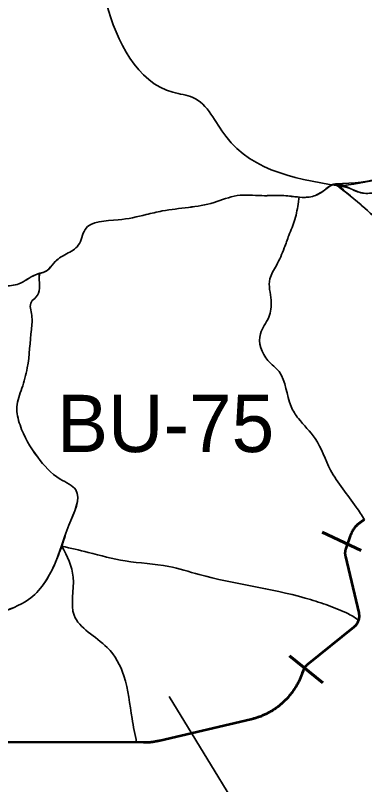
# Model space of a CAD drawing. Extents: x 553962 to 842807, y 8883888 to 9032388.
# Drawn here: x 661743 to 664180, y 8952165 to 8957536 of the extents above; entities that cross this region are included whole.
import ezdxf

# ---------------------------------------------------------------- set-up
doc = ezdxf.new("R2010")
doc.units = 0
doc.header["$LTSCALE"] = 150
for name, color, linetype, lineweight in [('20', 7, 'Continuous', 35), ('40', 7, 'Continuous', 60), ('60', 7, 'Continuous', 53), ('9', 7, 'Continuous', 90)]:
    doc.layers.add(name, color=color, linetype=linetype, lineweight=lineweight)

msp = doc.modelspace()

# ---------------------------------------------------------------- linework, layer by layer
at = {"layer": '20'}
for p, q in [((663983.2, 8956359), (663981.1, 8956359)), ((663983, 8956359.5), (663983.2, 8956359)), ((663725.2, 8956265.6), (663722.5, 8956265.9)), ((661914.8, 8955735.4), (661908.2, 8955709)), ((662067.8, 8953829.4), (662068, 8953829.2)), ((662068, 8953829.2), (662068.4, 8953831.3))]:
    msp.add_line(p, q, dxfattribs=at)
for points in [[(664136.3, 8953310.4), (664136.4, 8953310.8), (664137.2, 8953313.5), (664138, 8953316.2), (664138.6, 8953319), (664139.2, 8953321.8), (664139.7, 8953324.5), (664140.1, 8953327.3), (664140.5, 8953330.1), (664140.7, 8953333), (664140.9, 8953335.8), (664141, 8953338.6), (664141, 8953341.4), (664141, 8953344.3), (664140.8, 8953347.1), (664140.6, 8953349.9), (664140.3, 8953352.7), (664139.9, 8953355.5), (664139.5, 8953358.3), (664139, 8953361.1), (664138.3, 8953363.8), (664045.4, 8953756.9), (664045.3, 8953757.1), (664044.7, 8953759.9), (664044.2, 8953762.7), (664043.7, 8953765.5), (664043.4, 8953768.3), (664043.1, 8953771.1), (664042.9, 8953773.9), (664042.7, 8953776.7), (664042.7, 8953779.6), (664042.7, 8953782.4), (664042.8, 8953785.2), (664043, 8953788), (664043.3, 8953790.9), (664043.6, 8953793.7), (664044.1, 8953796.5), (664044.6, 8953799.2), (664045.2, 8953802), (664045.8, 8953804.8), (664046.6, 8953807.5), (664047.4, 8953810.2), (664048.3, 8953812.9), (664078.8, 8953900.5), (664078.9, 8953900.7), (664080.3, 8953904.5), (664081.7, 8953908.2), (664083.2, 8953911.9), (664084.8, 8953915.6), (664086.5, 8953919.2), (664088.2, 8953922.8), (664090, 8953926.4), (664091.9, 8953930), (664093.8, 8953933.5), (664095.8, 8953936.9), (664097.9, 8953940.3), (664100, 8953943.7), (664102.3, 8953947), (664104.5, 8953950.3), (664106.9, 8953953.6), (664109.3, 8953956.8), (664111.8, 8953959.9), (664114.3, 8953963), (664116.9, 8953966), (664119.6, 8953969), (664122.3, 8953972), (664125.1, 8953974.8), (664127.9, 8953977.7), (664130.8, 8953980.4), (664133.7, 8953983.1), (664136.7, 8953985.8), (664139.8, 8953988.4), (664142.9, 8953990.9), (664146, 8953993.4), (664149.2, 8953995.8), (664152.5, 8953998.1), (664155.8, 8954000.4), (664159.1, 8954002.6), (664162.5, 8954004.7), (664165.9, 8954006.8), (664169.4, 8954008.8), (664172.9, 8954010.7), (664176.4, 8954012.6), (664178.1, 8954013.4)], [(664109.7, 8953268.1), (664111.7, 8953270.1), (664113.7, 8953272.1), (664115.6, 8953274.2), (664117.4, 8953276.3), (664119.2, 8953278.5), (664121, 8953280.8), (664122.6, 8953283), (664124.2, 8953285.4), (664125.8, 8953287.7), (664127.2, 8953290.2), (664128.6, 8953292.6), (664130, 8953295.1), (664131.2, 8953297.6), (664132.4, 8953300.2), (664133.5, 8953302.8), (664134.6, 8953305.4), (664135.5, 8953308.1), (664135.7, 8953308.5)], [(663413.5, 8952626.8), (663419.5, 8952628.7), (663425.6, 8952630.6), (663431.6, 8952632.6), (663437.5, 8952634.6), (663443.5, 8952636.7), (663449.4, 8952638.9), (663455.3, 8952641.2), (663461.2, 8952643.6), (663467, 8952646), (663472.8, 8952648.5), (663478.6, 8952651.1), (663484.4, 8952653.7), (663490.1, 8952656.4), (663495.8, 8952659.2), (663501.4, 8952662.1), (663507, 8952665), (663512.6, 8952668), (663518.1, 8952671.1), (663523.6, 8952674.2), (663529, 8952677.5), (663534.4, 8952680.7), (663539.8, 8952684.1), (663545.1, 8952687.5), (663550.4, 8952691), (663555.6, 8952694.6), (663560.8, 8952698.2), (663566, 8952701.8), (663571.1, 8952705.6), (663576.1, 8952709.4), (663581.1, 8952713.3), (663586, 8952717.2), (663590.9, 8952721.2), (663595.8, 8952725.3), (663600.6, 8952729.4), (663605.3, 8952733.6), (663610, 8952737.8), (663614.7, 8952742.1), (663619.2, 8952746.5), (663623.8, 8952750.9), (663628.2, 8952755.4), (663632.6, 8952759.9), (663637, 8952764.5), (663641.3, 8952769.2), (663645.5, 8952773.8), (663649.7, 8952778.6), (663653.8, 8952783.4), (663657.9, 8952788.2), (663661.9, 8952793.2), (663665.8, 8952798.1), (663669.7, 8952803.1), (663673.5, 8952808.2), (663677.2, 8952813.3), (663680.9, 8952818.4), (663684.5, 8952823.6), (663688.1, 8952828.8), (663691.5, 8952834.1), (663694.9, 8952839.4), (663698.3, 8952844.8), (663701.6, 8952850.2), (663704.8, 8952855.7), (663707.9, 8952861.2), (663711, 8952866.7), (663714, 8952872.3), (663716.9, 8952877.9), (663719.8, 8952883.5), (663722.5, 8952889.2), (663725.2, 8952894.9), (663727.9, 8952900.7), (663730.5, 8952906.4), (663733, 8952912.2), (663735.4, 8952918.1), (663737.7, 8952924), (663740, 8952929.9), (663742.2, 8952935.8), (663744.3, 8952941.8), (663750.3, 8952958.8), (663750.9, 8952960.7), (663752, 8952963.3), (663753.1, 8952965.9), (663754.2, 8952968.5), (663755.5, 8952971.1), (663756.8, 8952973.6), (663758.2, 8952976), (663759.6, 8952978.5), (663761.1, 8952980.8), (663762.7, 8952983.2), (663764.4, 8952985.5), (663766.1, 8952987.7), (663767.9, 8952989.9), (663769.7, 8952992.1), (663771.6, 8952994.2), (663773.6, 8952996.2), (663775.6, 8952998.2), (663777.7, 8953000.1), (663779.8, 8953002), (663782, 8953003.8), (664103.8, 8953263), (664105.4, 8953264.3), (664107.6, 8953266.2), (664109.7, 8953268.1)], [(662589.5, 8952457.7), (662636.4, 8952457.6), (662639.1, 8952457.6), (662645.4, 8952457.6), (662651.7, 8952457.8), (662658, 8952458), (662664.3, 8952458.3), (662670.7, 8952458.7), (662677, 8952459.1), (662683.3, 8952459.7), (662689.6, 8952460.3), (662695.8, 8952461), (662702.1, 8952461.8), (662708.4, 8952462.6), (662714.7, 8952463.5), (662720.9, 8952464.6), (662727.1, 8952465.7), (662733.3, 8952466.8), (662739.5, 8952468.1), (662745.7, 8952469.4), (662751.9, 8952470.8), (663386.4, 8952619.7), (663389, 8952620.3), (663395.2, 8952621.8), (663401.3, 8952623.4), (663407.4, 8952625.1), (663413.5, 8952626.8)], [(661588, 8952460.2), (662586.9, 8952457.7)]]:
    msp.add_lwpolyline(points, dxfattribs=at)
for points in [[(658364.9, 8962599.6), (658556.5, 8962502.9), (659045.7, 8962575.2), (659677.7, 8962855.9), (660030.7, 8963073.8), (660994.7, 8963383.9), (661225.1, 8963375.6), (661485.9, 8963334), (661784, 8963142), (662145.1, 8962868.4), (662304.1, 8962730.4), (662407.6, 8962635.8), (662485.7, 8962526), (662573.8, 8962395.9), (662618.6, 8962222.6), (662640.7, 8962049.3), (662647.4, 8961832.8), (662600.5, 8961517.2), (662472.3, 8961166.2), (662328.2, 8960647.1), (662136.1, 8960143.5), (662172.6, 8959188.3), (662226.8, 8958808.7), (662270.5, 8958368), (662304.7, 8958064.8), (662378.8, 8957618.9), (662842.3, 8956998.6), (662981.5, 8956962.5), (663210.9, 8956691.8), (664058.5, 8956334.7)], [(663981.1, 8956359), (664321.5, 8956411.5), (664614.4, 8956608.1), (664864.3, 8956815.9), (665021.3, 8956998.4), (665311.2, 8957255.6), (665395.6, 8957334.1), (665677.4, 8957354.5), (665753.9, 8957347.5), (666009.5, 8957272.9), (666473.5, 8957092.1), (666601, 8956857), (666580.9, 8956718.8), (666458.2, 8956568.3), (666403.9, 8956491.1)], [(664028.5, 8956347.9), (664321.5, 8956411.5), (664614.4, 8956608.1), (664864.3, 8956815.9), (665021.3, 8956998.4), (665311.2, 8957255.6), (665395.6, 8957334.1), (665677.4, 8957354.5), (665753.9, 8957347.5), (666009.5, 8957272.9), (666473.5, 8957092.1), (666601, 8956857), (666580.9, 8956718.8), (666458.2, 8956568.3), (666395.8, 8956461.5), (666396.3, 8956401), (666405.5, 8956143.7), (666460.3, 8955877.6), (666486.7, 8955602.2), (666567.1, 8955262.4)], [(658265.6, 8954703.8), (658307.9, 8954697.9), (658477.4, 8954686), (658784.8, 8954711.4), (658906.1, 8954671.9), (659120.4, 8954604.2), (659357.3, 8954511.1), (659671.5, 8954424.1), (659815.3, 8954446.7), (659930.9, 8954686.6), (660012.7, 8954833.3), (660207.3, 8954937.7), (660675.5, 8955107.1), (660909.5, 8955188.9), (660962, 8955262.3), (660987.4, 8955304.6), (661066.3, 8955341.3), (661139.7, 8955386.4), (661204.5, 8955507.8), (661229.9, 8955575.5), (661294.8, 8955586.8), (661382.2, 8955586.8), (661505.5, 8955628), (661660.6, 8955644.9), (661767.7, 8955661.9), (661883.4, 8955724), (661965.2, 8955755), (662010.3, 8955805.8), (662100.5, 8955870.7), (662182.3, 8955930), (662229.4, 8956040), (662460.7, 8956107.8), (662655.3, 8956144.4), (662768.1, 8956169.8), (663129.1, 8956229.1), (663289.8, 8956276.8), (663461.8, 8956276.8), (663617, 8956276.8), (663815.8, 8956271.2), (663900.4, 8956316.3), (663976.5, 8956358.6), (664083.7, 8956324.8), (664176.8, 8956293.7), (664227.5, 8956293.7), (664439.1, 8956265.5), (664543.4, 8956211.9), (664670.3, 8956189.3)], [(664014.5, 8956353.1), (663976.5, 8956358.6), (663900.4, 8956316.3), (663815.8, 8956271.2), (663617, 8956276.8), (663461.8, 8956276.8), (663289.8, 8956276.8), (663129.1, 8956229.1), (662768.1, 8956169.8), (662655.3, 8956144.4), (662460.7, 8956107.8), (662229.4, 8956040), (662182.3, 8955930), (662100.5, 8955870.7), (662010.3, 8955805.8), (661965.2, 8955755), (661883.4, 8955724), (661767.7, 8955661.9), (661660.6, 8955644.9), (661505.5, 8955628), (661382.2, 8955586.8), (661294.8, 8955586.8), (661229.9, 8955575.5), (661204.5, 8955507.8), (661139.7, 8955386.4), (661066.3, 8955341.3), (660987.4, 8955304.6), (660962, 8955262.3), (660909.5, 8955188.9), (660675.5, 8955107.1), (660207.3, 8954937.7), (660012.7, 8954833.3), (659930.9, 8954686.6), (659815.3, 8954446.7), (659671.5, 8954424.1), (659357.3, 8954511.1), (659120.4, 8954604.2), (658906.1, 8954671.9), (658784.8, 8954711.4), (658477.4, 8954686), (658307.9, 8954697.9), (658265.6, 8954703.8)], [(663980.8, 8956358.9), (663976.5, 8956358.6), (663900.4, 8956316.3), (663815.8, 8956271.2), (663725.2, 8956265.6)], [(664755.7, 8954053.1), (664609.6, 8954383.1), (664511, 8954645), (664477, 8954750.4), (664388.6, 8954978.3), (664378.4, 8955318.5), (664378.4, 8955556.6), (664412.4, 8955879.7), (664181.2, 8956189.3), (663977.3, 8956356)], [(664755.7, 8954053.1), (664609.6, 8954383.1), (664511, 8954645), (664477, 8954750.4), (664388.6, 8954978.3), (664378.4, 8955318.5), (664378.4, 8955556.6), (664412.4, 8955879.7), (664181.2, 8956189.3), (663983, 8956359.5)], [(664755.7, 8954053.1), (664609.6, 8954383.1), (664511, 8954645), (664477, 8954750.4), (664388.6, 8954978.3), (664378.4, 8955318.5), (664378.4, 8955556.6), (664412.4, 8955879.7), (664181.2, 8956189.3), (663983, 8956359.5)], [(663983.2, 8956359), (664083.7, 8956324.8), (664176.8, 8956293.7), (664227.5, 8956293.7), (664439.1, 8956265.5), (664543.4, 8956211.9), (664670.3, 8956189.3)], [(664670.3, 8956189.3), (664543.4, 8956211.9), (664439.1, 8956265.5), (664227.5, 8956293.7), (664176.8, 8956293.7), (664083.7, 8956324.8), (663983.2, 8956359)], [(663723.7, 8956265.8), (663617, 8956276.8), (663461.8, 8956276.8), (663289.8, 8956276.8), (663129.1, 8956229.1), (662768.1, 8956169.8), (662655.3, 8956144.4), (662460.7, 8956107.8), (662229.4, 8956040), (662182.3, 8955930), (662100.5, 8955870.7), (662010.3, 8955805.8), (661965.2, 8955755), (661914.8, 8955735.4)], [(664179.3, 8954014.1), (664121.2, 8954102.5), (664027.1, 8954229.8), (663942.3, 8954361.1), (663834.3, 8954581.1), (663717.6, 8954721.7), (663667.2, 8954803.9), (663582.4, 8955047.9), (663505.5, 8955124.9), (663452.5, 8955313.2), (663510.8, 8955427.3), (663526.8, 8955546.6), (663518.8, 8955695.2), (663563.9, 8955789.6), (663619.5, 8955911.7), (663651.3, 8955999.2), (663693.8, 8956110.6), (663717.6, 8956232.6), (663722.5, 8956265.9)], [(663722.5, 8956265.9), (663717.6, 8956232.6), (663693.8, 8956110.6), (663651.3, 8955999.2), (663619.5, 8955911.7), (663563.9, 8955789.6), (663518.8, 8955695.2), (663526.8, 8955546.6), (663510.8, 8955427.3), (663452.5, 8955313.2), (663505.5, 8955124.9), (663582.4, 8955047.9), (663667.2, 8954803.9), (663717.6, 8954721.7), (663834.3, 8954581.1), (663942.3, 8954361.1), (664027.1, 8954229.8), (664121.2, 8954102.5), (664179.3, 8954014.1)], [(664179.3, 8954014.1), (664121.2, 8954102.5), (664027.1, 8954229.8), (663942.3, 8954361.1), (663834.3, 8954581.1), (663717.6, 8954721.7), (663667.2, 8954803.9), (663582.4, 8955047.9), (663505.5, 8955124.9), (663452.5, 8955313.2), (663510.8, 8955427.3), (663526.8, 8955546.6), (663518.8, 8955695.2), (663563.9, 8955789.6), (663619.5, 8955911.7), (663651.3, 8955999.2), (663693.8, 8956110.6), (663717.6, 8956232.6), (663722.5, 8956265.9)], [(659729.1, 8954415.6), (659815.3, 8954446.7), (659930.9, 8954686.6), (660012.7, 8954833.3), (660207.3, 8954937.7), (660675.5, 8955107.1), (660909.5, 8955188.9), (660962, 8955262.3), (660987.4, 8955304.6), (661066.3, 8955341.3), (661139.7, 8955386.4), (661204.5, 8955507.8), (661229.9, 8955575.5), (661294.8, 8955586.8), (661382.2, 8955586.8), (661505.5, 8955628), (661660.6, 8955644.9), (661767.7, 8955661.9), (661883.4, 8955724), (661914.3, 8955735.2)], [(661908.2, 8955709), (661910.2, 8955723.1), (661914.1, 8955735.2)], [(660977.5, 8952920.6), (661096, 8952973), (661231.9, 8952979.3), (661427.8, 8953197.5), (661626.9, 8953355.6), (661835.5, 8953456.8), (662015.6, 8953700.3), (662116.8, 8953975.5), (662164.2, 8954222.1), (662056.7, 8954298), (661898.7, 8954449.8), (661775.5, 8954675.6), (661753.3, 8954802.1), (661788.1, 8954931.7), (661826, 8955074), (661854.5, 8955342.8), (661857.6, 8955440.8), (661854.5, 8955535.7), (661886.1, 8955567.3), (661908.2, 8955709)], [(661908.2, 8955709), (661886.1, 8955567.3), (661854.5, 8955535.7), (661857.6, 8955440.8), (661854.5, 8955342.8), (661826, 8955074), (661788.1, 8954931.7), (661753.3, 8954802.1), (661775.5, 8954675.6), (661898.7, 8954449.8), (662056.7, 8954298), (662164.2, 8954222.1), (662116.8, 8953975.5), (662069, 8953832.8)], [(661908.2, 8955709), (661886.1, 8955567.3), (661854.5, 8955535.7), (661857.6, 8955440.8), (661854.5, 8955342.8), (661826, 8955074), (661788.1, 8954931.7), (661753.3, 8954802.1), (661775.5, 8954675.6), (661898.7, 8954449.8), (662056.7, 8954298), (662164.2, 8954222.1), (662116.8, 8953975.5), (662069, 8953832.8)], [(662068.4, 8953831.3), (662015.6, 8953700.3), (661835.5, 8953456.8), (661626.9, 8953355.6), (661427.8, 8953197.5), (661231.9, 8952979.3), (661096, 8952973), (660977.5, 8952920.6)], [(662068.4, 8953831.3), (662015.6, 8953700.3), (661835.5, 8953456.8), (661626.9, 8953355.6), (661427.8, 8953197.5), (661231.9, 8952979.3), (661096, 8952973), (660977.5, 8952920.6)], [(663911.6, 8953421.1), (663764.6, 8953467), (663025.1, 8953631.4), (662813.3, 8953688.3), (662509.9, 8953726.3), (662250.8, 8953786.3), (662067.8, 8953829.4)], [(662067.8, 8953829.4), (662250.8, 8953786.3), (662509.9, 8953726.3), (662813.3, 8953688.3), (663025.1, 8953631.4), (663764.6, 8953467), (663911.6, 8953421.1)], [(663911.6, 8953421.1), (663764.6, 8953467), (663025.1, 8953631.4), (662813.3, 8953688.3), (662509.9, 8953726.3), (662250.8, 8953786.3), (662067.8, 8953829.4)], [(662589, 8952457.7), (662557.3, 8952625.8), (662500.5, 8952923), (662383.5, 8953122.2), (662152.8, 8953346.8), (662146.5, 8953612.4), (662068, 8953829.3)], [(662589, 8952457.7), (662557.3, 8952625.8), (662500.5, 8952923), (662383.5, 8953122.2), (662152.8, 8953346.8), (662146.5, 8953612.4), (662068, 8953829.2)], [(662068, 8953829.2), (662146.5, 8953612.4), (662152.8, 8953346.8), (662383.5, 8953122.2), (662500.5, 8952923), (662557.3, 8952625.8), (662589, 8952457.7)], [(664136.7, 8953311.8), (664123.6, 8953322.2), (664048.3, 8953365.5), (663909.6, 8953421.4)], [(663909.6, 8953421.4), (664048.3, 8953365.5), (664123.6, 8953322.2), (664136.7, 8953311.8)]]:
    msp.add_spline(points, degree=3, dxfattribs=at)
at = {"layer": '40'}
for p, q in [((664155.7, 8953799.8), (663883.7, 8953926.3)), ((663655.3, 8953063), (663889, 8952874.9))]:
    msp.add_line(p, q, dxfattribs=at)
at = {"layer": '40', "lineweight": 35}
msp.add_lwpolyline([(662816.2, 8952778.7), (663534.6, 8951601), (665322.9, 8951601)], dxfattribs=at)
at = {"layer": '60'}
for points in [[(664180, 8954014.4), (664176.4, 8954012.6), (664172.9, 8954010.7), (664169.4, 8954008.8), (664165.9, 8954006.8), (664162.5, 8954004.7), (664159.1, 8954002.6), (664155.8, 8954000.4), (664152.5, 8953998.1), (664149.2, 8953995.8), (664146, 8953993.4), (664142.9, 8953990.9), (664139.8, 8953988.4), (664136.7, 8953985.8), (664133.7, 8953983.1), (664130.8, 8953980.4), (664127.9, 8953977.7), (664125.1, 8953974.8), (664122.3, 8953972), (664119.6, 8953969), (664116.9, 8953966), (664114.3, 8953963), (664111.8, 8953959.9), (664109.3, 8953956.8), (664106.9, 8953953.6), (664104.5, 8953950.3), (664102.3, 8953947), (664100, 8953943.7), (664097.9, 8953940.3), (664095.8, 8953936.9), (664093.8, 8953933.5), (664091.9, 8953930), (664090, 8953926.4), (664088.2, 8953922.8), (664086.5, 8953919.2), (664084.8, 8953915.6), (664083.2, 8953911.9), (664081.7, 8953908.2), (664080.3, 8953904.5), (664078.9, 8953900.7), (664078.8, 8953900.5), (664048.3, 8953812.9), (664047.4, 8953810.2), (664046.6, 8953807.5), (664045.8, 8953804.8), (664045.2, 8953802), (664044.6, 8953799.2), (664044.1, 8953796.5), (664043.6, 8953793.7), (664043.3, 8953790.9), (664043, 8953788), (664042.8, 8953785.2), (664042.7, 8953782.4), (664042.7, 8953779.6), (664042.7, 8953776.7), (664042.9, 8953773.9), (664043.1, 8953771.1), (664043.4, 8953768.3), (664043.7, 8953765.5), (664044.2, 8953762.7), (664044.7, 8953759.9), (664045.3, 8953757.1), (664045.4, 8953756.9), (664138.3, 8953363.8), (664139, 8953361.1), (664139.5, 8953358.3), (664139.9, 8953355.5), (664140.3, 8953352.7), (664140.6, 8953349.9), (664140.8, 8953347.1), (664141, 8953344.3), (664141, 8953341.4), (664141, 8953338.6), (664140.9, 8953335.8), (664140.7, 8953333), (664140.5, 8953330.1), (664140.1, 8953327.3), (664139.7, 8953324.5), (664139.2, 8953321.8), (664138.6, 8953319), (664138, 8953316.2), (664137.2, 8953313.5), (664136.4, 8953310.8), (664135.5, 8953308.1), (664134.6, 8953305.4), (664133.5, 8953302.8), (664132.4, 8953300.2), (664131.2, 8953297.6), (664130, 8953295.1), (664128.6, 8953292.6), (664127.2, 8953290.2), (664125.8, 8953287.7), (664124.2, 8953285.4), (664122.6, 8953283), (664121, 8953280.8), (664119.2, 8953278.5), (664117.4, 8953276.3), (664115.6, 8953274.2), (664113.7, 8953272.1), (664111.7, 8953270.1), (664109.7, 8953268.1)], [(664109.7, 8953268.1), (664107.6, 8953266.2), (664105.4, 8953264.3), (664103.8, 8953263), (663782, 8953003.8), (663779.8, 8953002), (663777.7, 8953000.1), (663775.6, 8952998.2), (663773.6, 8952996.2), (663771.6, 8952994.2), (663769.7, 8952992.1), (663767.9, 8952989.9), (663766.1, 8952987.7), (663764.4, 8952985.5), (663762.7, 8952983.2), (663761.1, 8952980.8), (663759.6, 8952978.5), (663758.2, 8952976), (663756.8, 8952973.6), (663755.5, 8952971.1), (663754.2, 8952968.5), (663753.1, 8952965.9), (663752, 8952963.3), (663750.9, 8952960.7), (663750.3, 8952958.8), (663744.3, 8952941.8), (663742.2, 8952935.8), (663740, 8952929.9), (663737.7, 8952924), (663735.4, 8952918.1), (663733, 8952912.2), (663730.5, 8952906.4), (663727.9, 8952900.7), (663725.2, 8952894.9), (663722.5, 8952889.2), (663719.8, 8952883.5), (663716.9, 8952877.9), (663714, 8952872.3), (663711, 8952866.7), (663707.9, 8952861.2), (663704.8, 8952855.7), (663701.6, 8952850.2), (663698.3, 8952844.8), (663694.9, 8952839.4), (663691.5, 8952834.1), (663688.1, 8952828.8), (663684.5, 8952823.6), (663680.9, 8952818.4), (663677.2, 8952813.3), (663673.5, 8952808.2), (663669.7, 8952803.1), (663665.8, 8952798.1), (663661.9, 8952793.2), (663657.9, 8952788.2), (663653.8, 8952783.4), (663649.7, 8952778.6), (663645.5, 8952773.8), (663641.3, 8952769.2), (663637, 8952764.5), (663632.6, 8952759.9), (663628.2, 8952755.4), (663623.8, 8952750.9), (663619.2, 8952746.5), (663614.7, 8952742.1), (663610, 8952737.8), (663605.3, 8952733.6), (663600.6, 8952729.4), (663595.8, 8952725.3), (663590.9, 8952721.2), (663586, 8952717.2), (663581.1, 8952713.3), (663576.1, 8952709.4), (663571.1, 8952705.6), (663566, 8952701.8), (663560.8, 8952698.2), (663555.6, 8952694.6), (663550.4, 8952691), (663545.1, 8952687.5), (663539.8, 8952684.1), (663534.4, 8952680.7), (663529, 8952677.5), (663523.6, 8952674.2), (663518.1, 8952671.1), (663512.6, 8952668), (663507, 8952665), (663501.4, 8952662.1), (663495.8, 8952659.2), (663490.1, 8952656.4), (663484.4, 8952653.7), (663478.6, 8952651.1), (663472.8, 8952648.5), (663467, 8952646), (663461.2, 8952643.6), (663455.3, 8952641.2), (663449.4, 8952638.9), (663443.5, 8952636.7), (663437.5, 8952634.6), (663431.6, 8952632.6), (663425.6, 8952630.6), (663419.5, 8952628.7), (663413.5, 8952626.8)], [(663413.5, 8952626.8), (663407.4, 8952625.1), (663401.3, 8952623.4), (663395.2, 8952621.8), (663389, 8952620.3), (663386.4, 8952619.7), (662751.9, 8952470.8), (662745.7, 8952469.4), (662739.5, 8952468.1), (662733.3, 8952466.8), (662727.1, 8952465.7), (662720.9, 8952464.6), (662714.7, 8952463.5), (662708.4, 8952462.6), (662702.1, 8952461.8), (662695.8, 8952461), (662689.6, 8952460.3), (662683.3, 8952459.7), (662677, 8952459.1), (662670.7, 8952458.7), (662664.3, 8952458.3), (662658, 8952458), (662651.7, 8952457.8), (662645.4, 8952457.6), (662639.1, 8952457.6), (662636.4, 8952457.6), (661588, 8952460.2)]]:
    msp.add_lwpolyline(points, dxfattribs=at)
at = {"layer": '9'}
msp.add_spline([(637260.6, 8972975.8), (641524.5, 8971056.2), (652526.1, 8965412.7), (653164.3, 8965062.8), (670790.5, 8953770.1), (686194, 8943929.9), (696283.3, 8937647.1)], degree=3, dxfattribs=at)

# ---------------------------------------------------------------- texts
at = {"layer": '40'}
msp.add_text('BU-75', height=400, dxfattribs=at).set_placement((662033, 8954486.6))

doc.saveas('drawing.dxf')
